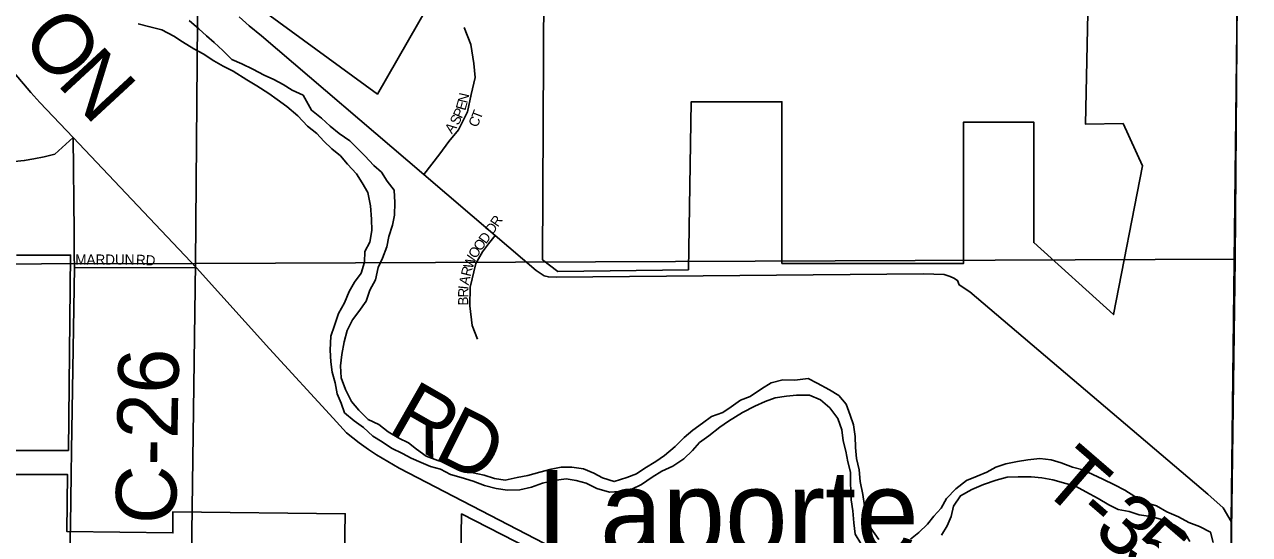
# Model space of a CAD drawing. Extents: x 1857828 to 2277390, y 930619 to 1324581.
# Drawn here: x 2080841 to 2086916, y 1214402 to 1216929 of the extents above; entities that cross this region are included whole.
import ezdxf

# ---------------------------------------------------------------- set-up
doc = ezdxf.new("R2010")
doc.units = 0
for name, color, linetype in [('GM_X_City_Street', 7, 'Continuous'), ('GM_X_Corporation', 7, 'Continuous'), ('GM_X_County_Road', 7, 'Continuous'), ('GM_X_County_Road_Text', 7, 'Continuous'), ('GM_X_Major_River', 7, 'Continuous'), ('GM_X_Section', 7, 'Continuous'), ('GM_X_Township', 7, 'Continuous'), ('GM_X_Township_Road', 7, 'Continuous'), ('GM_X_Township_Road_Text', 7, 'Continuous'), ('GM_X_Township_Subdivision', 7, 'Continuous'), ('GM_X_Township_Subdivision_Text', 7, 'Continuous'), ('GM_X_Unincorporated_Text', 7, 'Continuous')]:
    doc.layers.add(name, color=color, linetype=linetype)

msp = doc.modelspace()

# ---------------------------------------------------------------- linework, layer by layer
at = {"layer": 'GM_X_City_Street'}
msp.add_lwpolyline([(2081066.6, 1214346.6), (2081067.1, 1214378.9), (2081068.2, 1214450.4)], dxfattribs=at)
at = {"layer": 'GM_X_Corporation'}
for points in [[(2086118.6, 1217146), (2086103.5, 1216434.6), (2086289.6, 1216437.8), (2086385.8, 1216228.3), (2086242.6, 1215491.8), (2085846.5, 1215848.4), (2085846.5, 1216445.6), (2085498.1, 1216445.7), (2085498, 1215745.3), (2084597.5, 1215745.4), (2084597.7, 1216545.9), (2084147.5, 1216545.9), (2084133.4, 1215713.7), (2083485.5, 1215705.5), (2083410.7, 1215763.7), (2083417, 1217109.3)], [(2082891.8, 1217109.4), (2082591.5, 1216584.1), (2082041.3, 1216984.4)], [(2080801.1, 1215785.4), (2081069.2, 1215786.8), (2081058.7, 1214818.7), (2080706.5, 1214817.7)], [(2080705.1, 1214698.5), (2081053.7, 1214699.4), (2081050.6, 1214416.9), (2081576.7, 1214409.9), (2081576.9, 1214514.3), (2082431.7, 1214504.8), (2082426.4, 1214200.2)], [(2083003.5, 1214192.8), (2083008.7, 1214504.1), (2083340.5, 1214333.6)]]:
    msp.add_lwpolyline(points, dxfattribs=at)
at = {"layer": 'GM_X_County_Road'}
for points in [[(2084481.4, 1213642.1), (2084249.4, 1213874.3), (2084213, 1213908.4), (2084181.9, 1213938), (2084150, 1213963.7), (2084103.8, 1213997.9), (2084049, 1214032.5), (2083824.5, 1214148.2), (2082699.2, 1214730.9), (2082586.9, 1214795.9), (2082546.1, 1214823.7), (2082500.7, 1214856.2), (2082438.5, 1214905.4), (2082371.7, 1214977.8), (2082055.3, 1215322), (2081693.4, 1215722.8), (2081081.5, 1216369.5), (2080916.1, 1216542.2), (2080871.6, 1216592.1), (2080789.2, 1216690.2), (2080649.8, 1216892.8), (2080547.6, 1217082.7)], [(2081068.2, 1214450.4), (2081072, 1214699.4), (2081073.3, 1214818.6), (2081088.8, 1215724.3), (2081087.7, 1215787.4), (2081087.7, 1215900.8), (2081081.5, 1216369.5)]]:
    msp.add_lwpolyline(points, dxfattribs=at)
at = {"layer": 'GM_X_Major_River'}
for points in [[(2081404.9, 1216932), (2081463.1, 1216918.2), (2081521.3, 1216902.4), (2081581.6, 1216870.6), (2081623.8, 1216842.7), (2081680.1, 1216808.8), (2081726.3, 1216782.9), (2081780.6, 1216749.1), (2081826.8, 1216723.2), (2081875, 1216697.3), (2081943.3, 1216655.5), (2081993.6, 1216625.6), (2082051.9, 1216587.7), (2082094.1, 1216557.8), (2082142.4, 1216521.9), (2082196.7, 1216476), (2082245, 1216426), (2082291.3, 1216388.1), (2082325.6, 1216350.1), (2082365.8, 1216312.1), (2082408.1, 1216278.2), (2082442.3, 1216236.2), (2082486.6, 1216188.2), (2082514.9, 1216144.2), (2082543.1, 1216096.1), (2082557.5, 1216029.9), (2082561.7, 1215963.7), (2082564, 1215907.5), (2082554.2, 1215851.2), (2082528.3, 1215804.9), (2082526.6, 1215750.7), (2082510.8, 1215696.4), (2082476.9, 1215652), (2082451, 1215605.7), (2082427.2, 1215549.4), (2082397.3, 1215497), (2082377.5, 1215436.7), (2082359.7, 1215384.4), (2082356, 1215316.1), (2082360.3, 1215257.9), (2082366.5, 1215205.7), (2082380.8, 1215153.6), (2082391, 1215099.4), (2082411.3, 1215053.3), (2082427.5, 1215005.2), (2082475.8, 1214965.3), (2082522, 1214931.3), (2082568.3, 1214889.4), (2082614.5, 1214861.5), (2082660.8, 1214829.6), (2082715, 1214803.8), (2082759.2, 1214779.9), (2082807.4, 1214758.1), (2082853.6, 1214738.2), (2082903.8, 1214726.4), (2082954, 1214698.5), (2083006.2, 1214684.7), (2083066.4, 1214666.9), (2083122.7, 1214645.1), (2083180.9, 1214629.3), (2083237, 1214621.6), (2083297.2, 1214623.9), (2083355.3, 1214636.2), (2083409.3, 1214656.6), (2083465.4, 1214668.9), (2083527.5, 1214677.2), (2083577.6, 1214669.4), (2083625.8, 1214655.6), (2083680.1, 1214629.8), (2083742.3, 1214612), (2083792.4, 1214614.2), (2083852.5, 1214626.6), (2083900.5, 1214648.9), (2083954.5, 1214685.3), (2084002.5, 1214715.7), (2084056.5, 1214740), (2084110.5, 1214776.4), (2084154.4, 1214818.8), (2084188.3, 1214857.1), (2084234.3, 1214891.5), (2084290.2, 1214933.9), (2084332.2, 1214964.2), (2084402.2, 1215006.8), (2084462.2, 1215037.2)], [(2084602, 1215168.4), (2084543.9, 1215154), (2084495.9, 1215123.7), (2084439.9, 1215085.2), (2084391.9, 1215066.9), (2084345.9, 1215034.6), (2084303.9, 1215006.3), (2084247.9, 1214985.9), (2084203.9, 1214953.6), (2084156, 1214919.2), (2084112, 1214882.8), (2084068.1, 1214838.5), (2084014.2, 1214794), (2083972.2, 1214763.7), (2083918.2, 1214731.3), (2083876.2, 1214703), (2083828.2, 1214684.7), (2083766.1, 1214664.3), (2083707.9, 1214682.1), (2083663.7, 1214706), (2083613.5, 1214727.8), (2083555.3, 1214735.6), (2083503.2, 1214735.3), (2083453.1, 1214725), (2083397, 1214710.7), (2083337, 1214694.3), (2083284.9, 1214684.1), (2083224.8, 1214671.7), (2083172.6, 1214679.5), (2083120.5, 1214695.3), (2083058.2, 1214709.1), (2082996, 1214734.9), (2082947.8, 1214752.7), (2082891.6, 1214768.5), (2082833.4, 1214790.3), (2082785.1, 1214824.2), (2082744.9, 1214856.1), (2082696.7, 1214880), (2082644.4, 1214909.9), (2082598.1, 1214947.8), (2082545.9, 1214971.6), (2082499.6, 1215017.6), (2082463.3, 1215061.6), (2082433, 1215119.7), (2082410.7, 1215177.8), (2082408.5, 1215238), (2082414.2, 1215294.3), (2082426, 1215356.6), (2082441.8, 1215412.9), (2082467.6, 1215465.2), (2082499.5, 1215507.6), (2082535.4, 1215557.9), (2082553.2, 1215612.2), (2082581.1, 1215664.6), (2082594.8, 1215724.9), (2082616.7, 1215771.2), (2082638.5, 1215827.5), (2082648.3, 1215877.8), (2082666.1, 1215934.1), (2082675.9, 1215984.3), (2082677.7, 1216046.6), (2082673.4, 1216108.8), (2082639.1, 1216152.8), (2082610.9, 1216196.8), (2082572.6, 1216230.8), (2082528.3, 1216278.8), (2082492.1, 1216314.8), (2082453.9, 1216352.7), (2082401.6, 1216388.6), (2082357.3, 1216424.5), (2082313, 1216464.5), (2082264.8, 1216504.4), (2082222.3, 1216578.5), (2082168.1, 1216604.3), (2082123.9, 1216632.2), (2082077.7, 1216656.1), (2082029.5, 1216678), (2081973.2, 1216707.8), (2081919, 1216733.7), (2081868.7, 1216755.5), (2081824.5, 1216799.5), (2081782.2, 1216839.4), (2081743.9, 1216873.4), (2081705.7, 1216907.3), (2081657.4, 1216949.3)], [(2085078.4, 1214377.5), (2085038.1, 1214433.5), (2085021.8, 1214485.7), (2085007.6, 1214543.8), (2084999.3, 1214600), (2084985, 1214664.2), (2084980.7, 1214722.4), (2084966.5, 1214778.6), (2084962.2, 1214832.8), (2084960, 1214887), (2084951.7, 1214945.2), (2084935.5, 1214993.3), (2084915.2, 1215047.4), (2084878.9, 1215091.4), (2084832.7, 1215119.3), (2084772.4, 1215151.1), (2084728.2, 1215175), (2084662.1, 1215166.6), (2084602, 1215168.4)], [(2084462.2, 1215037.2), (2084514.2, 1215061.5), (2084564.2, 1215079.8), (2084620.3, 1215088.1), (2084670.4, 1215092.4), (2084734.6, 1215092.7), (2084788.8, 1215068.9), (2084835.1, 1215028.9), (2084875.4, 1214976.9), (2084893.7, 1214920.8), (2084901.9, 1214866.6), (2084914.2, 1214814.5), (2084924.4, 1214762.3), (2084936.7, 1214710.1), (2084936.9, 1214660), (2084941.3, 1214573.6), (2084949.5, 1214519.5), (2084953.8, 1214459.2), (2084960, 1214403), (2084988.3, 1214357)], [(2086736.4, 1214361.5), (2086722.2, 1214413.6), (2086667.9, 1214441.4), (2086615.7, 1214461.3), (2086563.5, 1214489.1), (2086507.2, 1214515), (2086455, 1214544.8), (2086398.8, 1214560.6), (2086348.5, 1214590.5), (2086298.3, 1214622.4), (2086246.1, 1214648.2), (2086189.8, 1214676.1), (2086139.6, 1214699.9), (2086089.4, 1214721.8), (2086039.2, 1214735.6), (2085983, 1214757.4), (2085932.8, 1214771.2), (2085876.6, 1214779), (2085816.5, 1214772.6), (2085766.4, 1214764.4), (2085708.3, 1214752.1), (2085658.3, 1214735.8), (2085614.3, 1214711.4), (2085566.3, 1214691.1), (2085512.2, 1214668.8), (2085460.3, 1214628.3), (2085414.4, 1214579.9), (2085386.5, 1214531.6), (2085350.6, 1214493.3), (2085318.7, 1214453), (2085276.8, 1214412.6), (2085234.8, 1214378.3)], [(2085389.1, 1214399.1), (2085417, 1214445.4), (2085436.8, 1214491.7), (2085448.6, 1214542), (2085482.5, 1214594.3), (2085538.5, 1214624.7), (2085596.5, 1214649.1), (2085660.6, 1214671.5), (2085714.6, 1214685.8), (2085768.8, 1214688.1), (2085832.9, 1214688.4), (2085887.1, 1214682.6), (2085941.2, 1214672.9), (2086005.4, 1214655.1), (2086053.6, 1214641.3), (2086103.9, 1214613.4), (2086166.1, 1214579.6), (2086218.4, 1214549.7), (2086264.6, 1214525.8), (2086318.8, 1214516.1), (2086369, 1214500.2), (2086427.1, 1214490.5), (2086493.4, 1214472.7), (2086547.6, 1214446.9), (2086591.9, 1214415), (2086620.1, 1214366.9)]]:
    msp.add_lwpolyline(points, dxfattribs=at)
at = {"layer": 'GM_X_Section'}
for points in [[(2079131.4, 1221341.6), (2081434.9, 1221340.3), (2081735.9, 1221339.4), (2081688.8, 1215745.2), (2076344.3, 1215732.7), (2076410.5, 1221338.4), (2078502.2, 1221340.9)], [(2084402.7, 1221331.9), (2086887.8, 1221326.7), (2086867.1, 1218558.1), (2086844.8, 1215767), (2081688.8, 1215745.2), (2081735.9, 1221339.4)], [(2076344.3, 1215732.7), (2081688.8, 1215745.2), (2081611.5, 1210047.1), (2076246.6, 1210012.2)], [(2086844.8, 1215767), (2086806.5, 1212949.4), (2086771.6, 1210288), (2086769.4, 1210081), (2081611.5, 1210047.1), (2081688.8, 1215745.2)]]:
    msp.add_lwpolyline(points, close=True, dxfattribs=at)
at = {"layer": 'GM_X_Township'}
for points in [[(2067771.4, 1221365.5), (2071559.9, 1221318), (2072926.4, 1221321.4), (2074729.4, 1221325.9), (2074869.3, 1221327.3), (2075410.3, 1221332.8), (2076347.8, 1221341.6), (2076980.3, 1221347.6), (2077896.6, 1221356.3), (2078876.9, 1221357.6), (2084360.8, 1221334.4), (2086459.3, 1221290.7), (2086885, 1221290.7), (2086885.2, 1220532.6), (2086868.6, 1218191.5), (2086826, 1214466.2), (2086824.4, 1213856.5), (2086823.8, 1213635.3), (2086822.7, 1213201.9), (2086821.5, 1212795.1), (2086788.3, 1211303.5), (2086791.5, 1211130), (2086792.2, 1211070.7), (2086754.4, 1208841.7)], [(2086754.4, 1208841.7), (2086792.2, 1211070.7), (2086791.5, 1211130), (2086788.3, 1211303.5), (2086821.5, 1212795.1), (2086822.7, 1213201.9), (2086823.8, 1213635.3), (2086824.4, 1213856.5), (2086826, 1214466.2), (2086868.6, 1218191.5), (2086885.2, 1220532.6), (2086885, 1221290.7), (2090249.5, 1221329.8)]]:
    msp.add_lwpolyline(points, dxfattribs=at)
at = {"layer": 'GM_X_Township_Road'}
for points in [[(2086826, 1214466.2), (2086856.9, 1217170.9)], [(2086826, 1214466.2), (2086786.3, 1214533.7), (2086710, 1214601.2), (2085530, 1215605), (2085475.7, 1215638.7), (2085467.6, 1215660.7), (2085449.5, 1215672.7), (2085431.5, 1215680.6), (2085401.3, 1215690.4), (2085299.2, 1215693.8), (2083477, 1215676.3), (2083438.9, 1215678.1), (2083418.9, 1215684), (2083378.7, 1215709.8), (2083174.8, 1215884), (2082820.9, 1216186.2), (2082016.6, 1216873.1), (2081954.3, 1216922.9), (2081906, 1216966.7)]]:
    msp.add_lwpolyline(points, dxfattribs=at)
at = {"layer": 'GM_X_Township_Subdivision'}
for points in [[(2082820.9, 1216186.2), (2082900.9, 1216288.5), (2082944.9, 1216349.2), (2082992.8, 1216407.6), (2083038.6, 1216496), (2083056.5, 1216582.3), (2083076.3, 1216666.7), (2083070, 1216736.4), (2083053.9, 1216829.1), (2083021.6, 1216913.3)], [(2081081.5, 1216369.5), (2080990.7, 1216285.9), (2080938, 1216273.2), (2080887.1, 1216264.1), (2080839.8, 1216255), (2080743.5, 1216245.9), (2079495.1, 1216244.1)], [(2083087.3, 1215370.5), (2083061.3, 1215436.7), (2083049.3, 1215535), (2083051.3, 1215627.3), (2083079.3, 1215745.3), (2083111.5, 1215801.9), (2083141.5, 1215842), (2083174.8, 1215884)], [(2081088.8, 1215724.3), (2081693.4, 1215722.8)]]:
    msp.add_lwpolyline(points, dxfattribs=at)

# ---------------------------------------------------------------- texts
at = {"layer": 'GM_X_County_Road_Text'}
for s, rotation, p in [('O', 308.8913, (2080815.7, 1216857.8)), ('N', 312.75106, (2080995.8, 1216635.7)), ('C-26', 88.96957, (2081591.9, 1214451.6)), ('R', 330.24253, (2082632.9, 1214912.5)), ('D', 333.29743, (2082861.9, 1214782.1))]:
    msp.add_text(s, height=300, rotation=rotation, dxfattribs=at).set_placement(p)
at = {"layer": 'GM_X_Township_Road_Text'}
for s, rotation, p in [('T', 319.21927, (2085869.8, 1214636.1)), ('3', 319.22485, (2086133, 1214409)), ('-', 319.22863, (2086039.7, 1214489.5)), ('5', 319.29876, (2086273.3, 1214288.1))]:
    msp.add_text(s, height=300, rotation=rotation, dxfattribs=at).set_placement(p)
at = {"layer": 'GM_X_Township_Subdivision_Text'}
for s, rotation, p in [('E', 74.07022, (2083026.6, 1216499.7)), ('N', 77.12311, (2083037, 1216536.3)), ('S', 62.3628, (2082991.5, 1216426.2)), ('P', 65.32119, (2083009.1, 1216459.9)), ('C', 65.91176, (2083085.3, 1216415.5)), ('T', 69.03346, (2083102.6, 1216454.4)), ('A', 53.17382, (2082960.5, 1216383.6)), ('D', 55.50357, (2083163.2, 1215885.8)), ('R', 55.50594, (2083188.1, 1215922.1)), ('O', 53.45358, (2083102.8, 1215802.2)), ('D', 54.52942, (2083129.6, 1215838.4)), ('O', 58.79632, (2083080.7, 1215765.6)), ('MARDUN', 0.00001, (2081092.7, 1215739.4)), ('RD', 356.98842, (2081392.4, 1215739.3)), ('W', 69.52268, (2083061.8, 1215714.3)), ('R', 75.56309, (2083052.3, 1215677.3)), ('R', 89.58727, (2083041.4, 1215575.9)), ('I', 84.3068, (2083041.6, 1215614.2)), ('A', 78.38147, (2083043.6, 1215634.8)), ('B', 89.78149, (2083041.3, 1215536.3))]:
    msp.add_text(s, height=50, rotation=rotation, dxfattribs=at).set_placement(p)
at = {"layer": 'GM_X_Unincorporated_Text'}
msp.add_text('Laporte', height=417, rotation=0.00001, dxfattribs=at).set_placement((2083385.1, 1214304.1))

doc.saveas('drawing.dxf')
